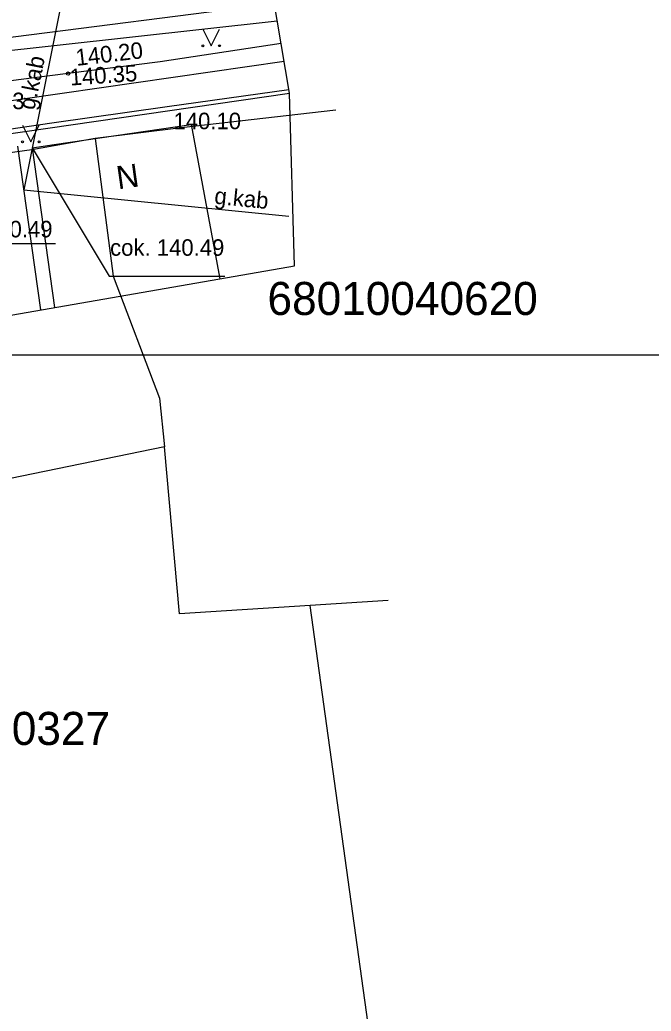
# Model space of a CAD drawing. Extents: x 728710 to 728960, y 272811 to 273475.
# Drawn here: x 728821.41 to 728840.52, y 273182.19 to 273212.21 of the extents above; entities that cross this region are included whole.
import ezdxf

# ---------------------------------------------------------------- set-up
doc = ezdxf.new("R2010")
doc.units = 0
for name, color, linetype in [('58', 7, 'Continuous'), ('Level 17', 7, 'Continuous'), ('Level 3', 7, 'Continuous'), ('Level 4', 7, 'Continuous'), ('Level 41', 7, 'Continuous'), ('Level 45', 7, 'Continuous'), ('Level 48', 7, 'Continuous'), ('Level 50', 7, 'Continuous'), ('Level 57', 7, 'Continuous'), ('Level 59', 7, 'Continuous'), ('Level 9', 7, 'Continuous'), ('RAMI_PLAN_####_TKST_#', 7, 'Continuous'), ('RAMI_UZMR_####_####_#', 7, 'Continuous'), ('ROBZ_ELEM_####_####_#', 7, 'Continuous'), ('ROBZ_KADS_####_TKST_#', 7, 'Continuous'), ('ROBZ_UZMR_####_####_#', 7, 'Continuous'), ('SAKT_VADV_PKAB_TKST_#', 7, 'Continuous'), ('TERT_KONT_####_####_#', 7, 'Continuous')]:
    doc.layers.add(name, color=color, linetype=linetype)

msp = doc.modelspace()

# ---------------------------------------------------------------- linework, layer by layer
at = {"layer": 'Level 17'}
msp.add_line((728804.594, 273209.577), (728829.118, 273212.697), dxfattribs=at)
at = {"layer": 'Level 3'}
for p, q in [((728822.448, 273208.432), (728826.597, 273209.036)), ((728826.597, 273209.036), (728827.464, 273204.366)), ((728821.783, 273208.335), (728822.448, 273208.432)), ((728821.345, 273208.386), (728822.042, 273203.423)), ((728821.783, 273208.335), (728822.46, 273203.495))]:
    msp.add_line(p, q, dxfattribs=at)
at = {"layer": 'Level 4'}
for p, q in [((728825.657, 273210.943), (728829.32, 273211.503)), ((728822.238, 273210.509), (728825.657, 273210.943)), ((728818.311, 273210.011), (728822.238, 273210.509)), ((728825.871, 273209.58), (728829.557, 273210.102)), ((728822.382, 273209.083), (728825.871, 273209.58)), ((728818.428, 273208.52), (728822.382, 273209.083))]:
    msp.add_line(p, q, dxfattribs=at)
at = {"layer": 'Level 41'}
msp.add_lwpolyline([(728792.122, 273205.478), (728819.326, 273209.502), (728829.414, 273210.952)], dxfattribs=at)
at = {"layer": 'Level 45'}
msp.add_lwpolyline([(728811.146, 273209.084), (728815.965, 273210.711), (728829.206, 273212.18)], dxfattribs=at)
at = {"layer": 'Level 48'}
msp.add_circle((728822.875, 273210.581), 0.05, dxfattribs=at)
at = {"layer": 'Level 9'}
for points in [[(728821.783, 273208.335), (728824.114, 273204.441), (728827.622, 273204.441)], [(728817.481, 273207.843), (728818.644, 273205.437), (728822.493, 273205.437)]]:
    msp.add_lwpolyline(points, dxfattribs=at)
at = {"layer": 'RAMI_PLAN_####_TKST_#'}
for points in [[(728728.89, 273202.048), (728728.89, 273475.126), (728912.915, 273475.126), (728912.915, 273202.048)], [(728709.938, 272811.037), (728959.516, 272811.036), (728959.516, 273202.048), (728709.939, 273202.048)]]:
    msp.add_lwpolyline(points, close=True, dxfattribs=at)
at = {"layer": 'RAMI_UZMR_####_####_#'}
for points in [[(728838.026, 273158.297), (728833.202, 273166.507), (728833.235, 273168.344), (728821.579, 273179.812), (728818.749, 273194.545), (728819.331, 273202.951), (728829.731, 273204.761), (728829.577, 273209.987), (728827.575, 273221.822), (728826.396, 273224.831), (728813.325, 273229.618), (728810.773, 273260.978), (728802.611, 273315.901)], [(728824.437, 273221.588), (728821.531, 273207.064)], [(728821.531, 273207.064), (728829.558, 273206.261)]]:
    msp.add_lwpolyline(points, dxfattribs=at)
at = {"layer": 'ROBZ_ELEM_####_####_#'}
msp.add_lwpolyline([(728811.24, 273207.332), (728829.577, 273209.987)], dxfattribs=at)
at = {"layer": 'ROBZ_UZMR_####_####_#'}
for p, q in [((728830.975, 273209.471), (728826.293, 273208.935)), ((728826.293, 273208.935), (728823.694, 273208.616)), ((728823.694, 273208.616), (728821.78, 273208.272)), ((728823.694, 273208.616), (728824.237, 273204.442)), ((728821.78, 273208.272), (728811.158, 273206.807)), ((728824.237, 273204.442), (728825.643, 273200.753)), ((728825.643, 273200.753), (728825.793, 273199.272)), ((728825.793, 273199.272), (728812.658, 273196.583)), ((728826.247, 273194.223), (728825.793, 273199.272)), ((728832.558, 273194.622), (728830.205, 273194.473)), ((728830.205, 273194.473), (728826.247, 273194.223)), ((728832.052, 273181.133), (728830.205, 273194.473))]:
    msp.add_line(p, q, dxfattribs=at)
at = {"layer": 'TERT_KONT_####_####_#'}
for p, q in [((728826.956, 273211.922), (728827.206, 273211.422)), ((728827.206, 273211.422), (728827.456, 273211.922)), ((728821.497, 273209.013), (728821.747, 273208.513)), ((728821.747, 273208.513), (728821.997, 273209.013))]:
    msp.add_line(p, q, dxfattribs=at)
for centre, radius in [((728826.956, 273211.421), 0.028), ((728827.456, 273211.421), 0.0263), ((728821.497, 273208.512), 0.028), ((728821.997, 273208.512), 0.0263)]:
    msp.add_circle(centre, radius, dxfattribs=at)

# ---------------------------------------------------------------- texts
at = {"layer": '58'}
msp.add_text(' 140.43', height=0.5, dxfattribs=at).set_placement((728819.326, 273209.502))
at = {"layer": 'Level 50'}
for p in [(728818.947, 273205.62), (728824.146, 273205.062)]:
    msp.add_text('cok. 140.49', height=0.5, dxfattribs=at).set_placement(p)
at = {"layer": 'Level 57'}
for s, rotation, p in [('140.20', 6.6378, (728823.132, 273210.811)), ('140.35', 3.8644, (728822.941, 273210.216))]:
    msp.add_text(s, height=0.5, rotation=rotation, dxfattribs=at).set_placement(p)
msp.add_text(' 140.10', height=0.5, dxfattribs=at).set_placement((728825.879, 273208.895))
at = {"layer": 'Level 59'}
msp.add_text('N', height=0.7, rotation=7.992, dxfattribs=at).set_placement((728824.388, 273207.072))
at = {"layer": 'ROBZ_KADS_####_TKST_#'}
for s, p in [('68010040620', (728828.909, 273203.27)), ('68010040327', (728815.964, 273190.25))]:
    msp.add_text(s, height=1, dxfattribs=at).set_placement(p)
at = {"layer": 'SAKT_VADV_PKAB_TKST_#'}
for rotation, p in [(78.6848, (728821.856, 273209.457)), (354.2853, (728827.287, 273206.639))]:
    msp.add_text('g.kab', height=0.5, rotation=rotation, dxfattribs=at).set_placement(p)

doc.saveas('drawing.dxf')
